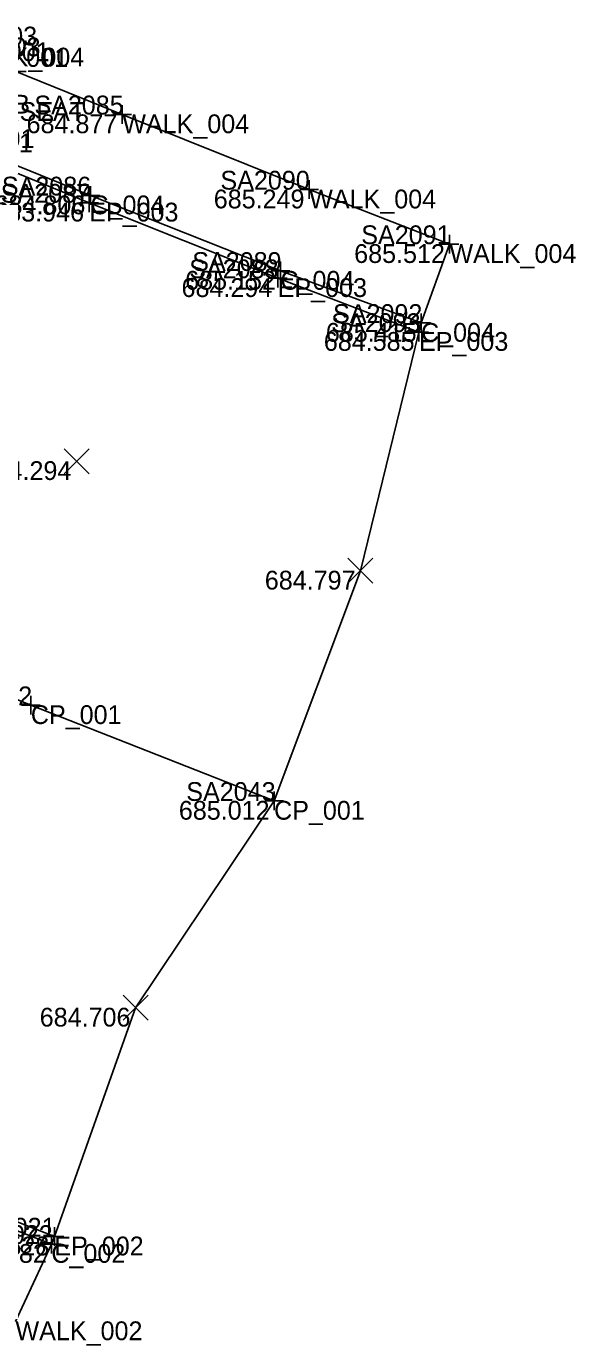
# Model space of a CAD drawing. Extents: x 1460264 to 1460899, y 578046 to 578200.
# Drawn here: x 1460322.2 to 1460351.4, y 578113.4 to 578183.6 of the extents above; entities that cross this region are included whole.
import ezdxf

# ---------------------------------------------------------------- set-up
doc = ezdxf.new("R2010")
doc.units = 0
for name, color, linetype in [('BR_X_SV_Beam_Seat', 7, 'Continuous'), ('BR_X_SV_Bottom_of_Beam_Text', 7, 'Continuous'), ('PV_X_COP', 7, 'Continuous'), ('PV_X_Curb', 7, 'Continuous'), ('PV_X_EOP', 7, 'Continuous'), ('PV_X_Walk', 7, 'Continuous'), ('SC_Scratch1', 7, 'Continuous'), ('SV_X_Random_Point', 7, 'Continuous'), ('SV_X_Shot_Marker', 7, 'Continuous'), ('SV_X_Text_Comment', 7, 'Continuous'), ('SV_X_Text_Elevation', 7, 'Continuous'), ('SV_X_Text_Name', 7, 'Continuous')]:
    doc.layers.add(name, color=color, linetype=linetype)

msp = doc.modelspace()

# ---------------------------------------------------------------- linework, layer by layer
at = {"layer": 'PV_X_COP'}
msp.add_lwpolyline([(1460306.747, 578153.858), (1460322.394, 578147.491), (1460335.353, 578142.398)], dxfattribs=at)
at = {"layer": 'PV_X_Curb'}
for points in [[(1460316.899, 578178.147), (1460325.57, 578174.633), (1460335.691, 578170.616), (1460343.184, 578167.846)], [(1460323.488, 578118.805), (1460309.836, 578124.1), (1460296.746, 578129.539)]]:
    msp.add_lwpolyline(points, dxfattribs=at)
at = {"layer": 'PV_X_EOP'}
for points in [[(1460316.763, 578177.825), (1460325.5, 578174.249), (1460335.547, 578170.229), (1460343.075, 578167.362)], [(1460296.717, 578129.998), (1460309.987, 578124.561), (1460323.647, 578119.2)]]:
    msp.add_lwpolyline(points, dxfattribs=at)
at = {"layer": 'PV_X_Walk'}
msp.add_lwpolyline([(1460318.475, 578182.502), (1460327.265, 578178.951), (1460337.223, 578174.947), (1460344.695, 578172.042)], dxfattribs=at)
at = {"layer": 'SC_Scratch1'}
msp.add_lwpolyline([(1460321.576, 578114.684), (1460323.488, 578118.805), (1460323.647, 578119.2), (1460327.972, 578131.383), (1460335.353, 578142.398), (1460339.955, 578154.652), (1460343.075, 578167.362), (1460343.184, 578167.846), (1460344.695, 578172.042), (1460337.223, 578174.947), (1460327.265, 578178.951), (1460318.475, 578182.502)], dxfattribs=at)
at = {"layer": 'SV_X_Random_Point'}
for p, q in [((1460324.175, 578159.818), (1460325.508, 578161.153)), ((1460324.175, 578161.153), (1460325.508, 578159.818)), ((1460339.289, 578153.985), (1460340.622, 578155.32)), ((1460339.289, 578155.32), (1460340.622, 578153.985)), ((1460327.306, 578130.715), (1460328.639, 578132.05)), ((1460327.306, 578132.05), (1460328.639, 578130.715))]:
    msp.add_line(p, q, dxfattribs=at)
at = {"layer": 'SV_X_Shot_Marker'}
for p, q in [((1460327.265, 578179.451), (1460327.265, 578178.451)), ((1460326.765, 578178.951), (1460327.765, 578178.951)), ((1460327.265, 578178.951), (1460327.265, 578178.951)), ((1460325.57, 578175.133), (1460325.57, 578174.133)), ((1460337.223, 578175.447), (1460337.223, 578174.447)), ((1460325.07, 578174.633), (1460326.07, 578174.633)), ((1460325.5, 578174.749), (1460325.5, 578173.749)), ((1460325.57, 578174.633), (1460325.57, 578174.633)), ((1460336.723, 578174.947), (1460337.723, 578174.947)), ((1460337.223, 578174.947), (1460337.223, 578174.947)), ((1460325, 578174.249), (1460326, 578174.249)), ((1460325.5, 578174.249), (1460325.5, 578174.249)), ((1460344.695, 578172.542), (1460344.695, 578171.542)), ((1460344.195, 578172.042), (1460345.195, 578172.042)), ((1460344.695, 578172.042), (1460344.695, 578172.042)), ((1460335.691, 578171.116), (1460335.691, 578170.116)), ((1460335.047, 578170.229), (1460336.047, 578170.229)), ((1460335.191, 578170.616), (1460336.191, 578170.616)), ((1460335.547, 578170.729), (1460335.547, 578169.729)), ((1460335.547, 578170.229), (1460335.547, 578170.229)), ((1460335.691, 578170.616), (1460335.691, 578170.616)), ((1460343.184, 578168.346), (1460343.184, 578167.346)), ((1460342.684, 578167.846), (1460343.684, 578167.846)), ((1460343.075, 578167.862), (1460343.075, 578166.862)), ((1460343.184, 578167.846), (1460343.184, 578167.846)), ((1460342.575, 578167.362), (1460343.575, 578167.362)), ((1460343.075, 578167.362), (1460343.075, 578167.362)), ((1460322.394, 578147.991), (1460322.394, 578146.991)), ((1460321.894, 578147.491), (1460322.894, 578147.491)), ((1460322.394, 578147.491), (1460322.394, 578147.491)), ((1460335.353, 578142.898), (1460335.353, 578141.898)), ((1460334.853, 578142.398), (1460335.853, 578142.398)), ((1460335.353, 578142.398), (1460335.353, 578142.398)), ((1460323.647, 578119.7), (1460323.647, 578118.7)), ((1460323.147, 578119.2), (1460324.147, 578119.2)), ((1460323.488, 578119.305), (1460323.488, 578118.305)), ((1460323.647, 578119.2), (1460323.647, 578119.2)), ((1460322.988, 578118.805), (1460323.988, 578118.805)), ((1460323.488, 578118.805), (1460323.488, 578118.805))]:
    msp.add_line(p, q, dxfattribs=at)

# ---------------------------------------------------------------- texts
at = {"layer": 'BR_X_SV_Beam_Seat'}
msp.add_text('BRSEAT', height=1, dxfattribs=at).set_placement((1460319.939, 578178.605))
at = {"layer": 'BR_X_SV_Bottom_of_Beam_Text'}
msp.add_text('BOB', height=1, dxfattribs=at).set_placement((1460319.528, 578178.996))
at = {"layer": 'SV_X_Text_Comment'}
for s, p in [('WALK_003', (1460315.966, 578182.623)), ('PAD_003', (1460317.187, 578182.044)), ('LINE_001', (1460317.447, 578181.784)), ('WALK_004', (1460318.475, 578181.502)), ('LINE_001', (1460318.432, 578181.484)), ('WALK_004', (1460327.265, 578177.951)), ('LINE_001', (1460316.555, 578176.928)), ('LINE_001', (1460316.639, 578177.16)), ('C_004', (1460325.57, 578173.633)), ('WALK_004', (1460337.223, 578173.947)), ('EP_003', (1460325.5, 578173.249)), ('WALK_004', (1460344.695, 578171.042)), ('EP_003', (1460335.547, 578169.229)), ('C_004', (1460335.691, 578169.616)), ('EP_003', (1460343.075, 578166.362)), ('C_004', (1460343.184, 578166.846)), ('CP_001', (1460322.394, 578146.491)), ('CP_001', (1460335.353, 578141.398)), ('EP_002', (1460323.647, 578118.2)), ('C_002', (1460323.488, 578117.805)), ('WALK_002', (1460321.576, 578113.684))]:
    msp.add_text(s, height=1, dxfattribs=at).set_placement(p)
at = {"layer": 'SV_X_Text_Elevation'}
for s, p in [('684.877', (1460322.17, 578177.951)), ('684.806', (1460320.465, 578173.633)), ('685.249', (1460332.14, 578173.947)), ('683.946', (1460320.395, 578173.249)), ('685.512', (1460339.622, 578171.042)), ('684.294', (1460330.425, 578169.229)), ('685.152', (1460330.618, 578169.616)), ('684.585', (1460338.005, 578166.362)), ('685.415', (1460338.113, 578166.846)), ('684.294', (1460319.72, 578159.486)), ('684.797', (1460334.86, 578153.652)), ('685.012', (1460330.28, 578141.398)), ('684.706', (1460322.868, 578130.383)), ('684.528', (1460318.547, 578118.2)), ('685.382', (1460318.415, 578117.805))]:
    msp.add_text(s, height=1, dxfattribs=at).set_placement(p)
at = {"layer": 'SV_X_Text_Name'}
for s, p in [('SA2085', (1460322.582, 578178.951)), ('SA2090', (1460332.496, 578174.947)), ('SA2087', (1460320.791, 578174.249)), ('SA2086', (1460320.852, 578174.633)), ('SA2091', (1460340, 578172.042)), ('SA2089', (1460330.994, 578170.616)), ('SA2088', (1460330.833, 578170.229)), ('SA2092', (1460338.497, 578167.846)), ('SA2093', (1460338.398, 578167.362)), ('SA2042', (1460317.708, 578147.491)), ('SA2043', (1460330.676, 578142.398)), ('SA2022', (1460318.802, 578118.805)), ('SA2021', (1460318.952, 578119.2))]:
    msp.add_text(s, height=1, dxfattribs=at).set_placement(p)

doc.saveas('drawing.dxf')
